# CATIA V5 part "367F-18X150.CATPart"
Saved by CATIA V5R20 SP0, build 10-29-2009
Part number: 367F-18X150
Definition: NONE
Nomenclature: 367F-18X150
Source: Unknown
Description: 367F-18X150
Bounding box of the stored display mesh (mm): x 0 to 150, y -14 to 14, z -14 to 14
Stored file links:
  C:\Users\Utente\Desktop\IO LAVORO\3D X SITO CF\X SITO\PLASTICA\3D files 367\367F-18X150.CATPart
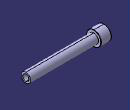
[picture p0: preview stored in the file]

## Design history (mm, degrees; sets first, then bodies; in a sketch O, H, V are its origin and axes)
Body1 "367F-18X150" (main body)
  Solid1: solid without history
